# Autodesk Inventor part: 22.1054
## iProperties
Created: 2007-01
Part Number: 22.1054
Document SubType Name: Modeling
Designer: Andy Moles
Material: ABS Plastic
Density: 1.06 g/cm^3
Mass: 4.21262 g
Surface Area: 32.835 cm^2
Volume: 3.97417 cm^3
Description: END CAP FOR HANDLE PROFILE RIGHT GRAY
Vendor: S
Author: Andy Moles
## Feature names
1. Base1
